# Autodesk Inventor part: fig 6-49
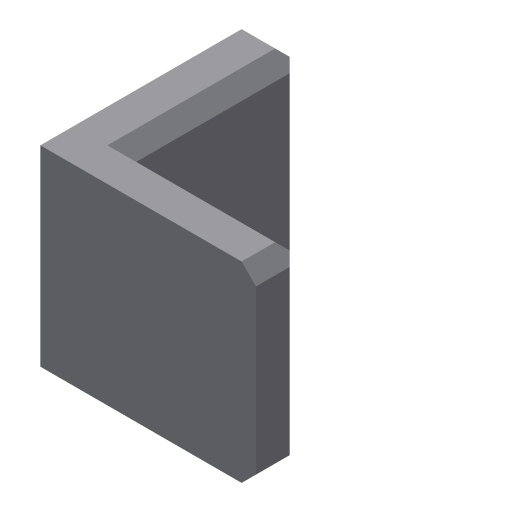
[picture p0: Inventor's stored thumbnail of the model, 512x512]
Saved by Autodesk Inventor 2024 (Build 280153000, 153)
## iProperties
Created: 2009-09
Part Number: fig 6-49
Document SubType Name: Modeling
Designer: Sham
Density: 1 g/cm^3
Material: Generic
Appearance: Default
Author: Sham
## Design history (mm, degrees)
sketch "Sketch1"
  geometry: L1 (1.789, 30)-(1.789, -5); L2 (1.789, -5)-(36.789, -5); L3 (36.789, -5)-(36.789, -15); L4 (36.789, -15)-(-8.211, -15); L5 (-8.211, -15)-(-8.211, 30); L6 (-8.211, 30)-(1.789, 30)
  constraints: 12 end point, 6 perpendicular
  dimensions: "d0" = 10 distance of L5.end L1.start; "d1" = 35 distance of L1.start L1.end; "d2" = 45 distance of L3.end L4.end; "d3" = 10 distance of L2.end L3.end (derived)
extrude "Extrusion1" new body sketch "Sketch1" distance "d4" = 40; taper "d5" = 0 deg
chamfer "Chamfer1" distance "d6" = 3; stored, may be unused: second distance "d7" = 2, angle "d8" = 45 deg
body "Solid1"
other parameters: "d1" = 35
